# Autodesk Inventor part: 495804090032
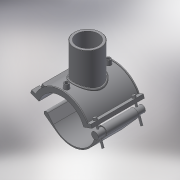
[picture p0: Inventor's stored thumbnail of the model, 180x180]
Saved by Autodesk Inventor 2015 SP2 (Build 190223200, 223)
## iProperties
Created: 2017-07
Part Number: 495804090032
Material: Generic
Description: PLASSON BRANCH SADDLE 90-32
Document SubType Name: Modeling
Designer: KIM
Density: 1 g/cm^3
Appearance: Default
Author: KIM
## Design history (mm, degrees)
derived "495804.ipt"
feature "Solid1::495804.ipt"
feature "Solid2::495804.ipt"
tag "TaggingFeature1"
body "Solid1"
body "Solid2"
other parameters: "d2" = 126, "d3" = 22.5, "d4" = 118, "d5" = 0, "d6" = 0.1, "d8" = 0, "d19" = 6, "d20" = 6, "d21" = 70.8, "d23" = 0, "d24" = 35.4, "d26" = 0, "d27" = 3, "d28" = 3, "d29" = 3, "d31" = 6, "d32" = 0, "d33" = 0, "d34" = 0.6, "d40" = 57.2, "d41" = 35.2, "d43" = 0, "d45" = 0, "d47" = 114, "d48" = 32, "d50" = 0, "d70" = 15, "d72" = 0, "d73" = 6, "d75" = 5, "d76" = 0, "d77" = 4.5, "d78" = 75, "d79" = 15, "d80" = 47.2, "d82" = 5 deg, "d84" = 4, "d85" = 14, "d86" = 0, "d87" = 3, "d88" = 0, "d89" = 1, "d90" = 1, "d91" = 94.4, "d92" = 0, "d93" = 0.5, "d94" = 47.36842, "d96" = 112.2, "d97" = 2.36, "d98" = 0, "d102" = 0.96, "d103" = 25.6, "d105" = 0, "d109" = -19.66667, "d117" = 0.32, "d120" = 140 deg, "d121" = 24.228, "d122" = 20 deg, "d124" = 66, "d126" = 0, "d143" = 94.5, "d150" = 16.2, "d159" = 4, "d161" = 2.25, "d162" = 70.8, "d163" = 0, "d167" = 18, "d173" = 1, "d175" = 45, "d176" = 20 deg, "d177" = 6.3, "d180" = 0, "d185" = 38.35, "d186" = 38.35, "d187" = 55, "d188" = 6, "d189" = 6.3, "d190" = 0, "d191" = 82.5, "d202" = 0, "d216" = 106.2, "d217" = 0, "d221" = 43.66, "d222" = 6.3, "d223" = 3.78, "d224" = 45, "d225" = 3.78, "d227" = 12.96, "d230" = 55.8, "d236" = 20 deg, "d237" = 62, "d238" = 20 deg, "d239" = 6.3, "B_" = 126, "H_" = 59, "L_" = 118, "d_t" = 6, "d_1" = 32, "H_1" = 49, "d148" = 2.25, "d160" = 2.25
